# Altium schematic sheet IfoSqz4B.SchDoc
size C; Engineer: Daniel Sigg; DocumentNumber: 9; SheetNumber: 21; SheetTotal: 33
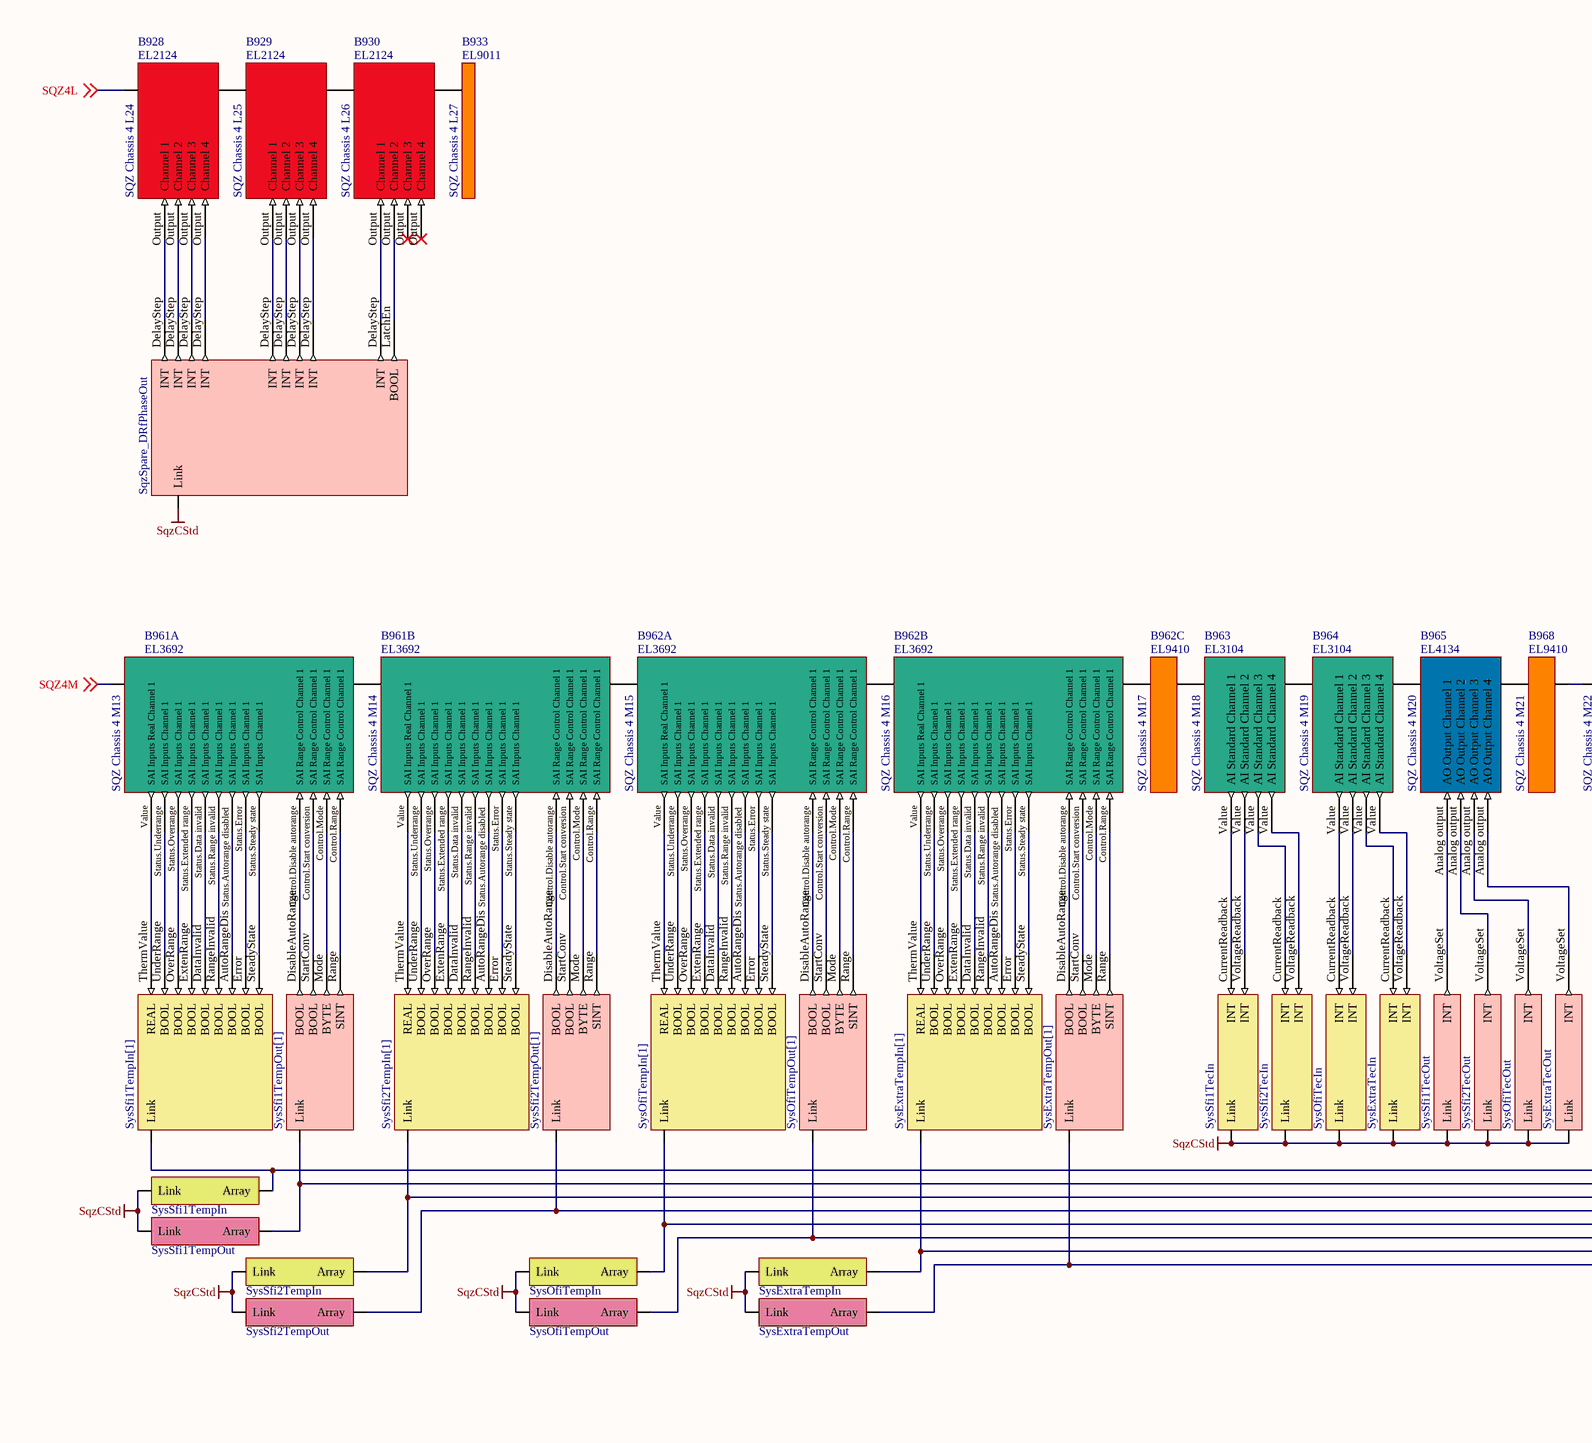
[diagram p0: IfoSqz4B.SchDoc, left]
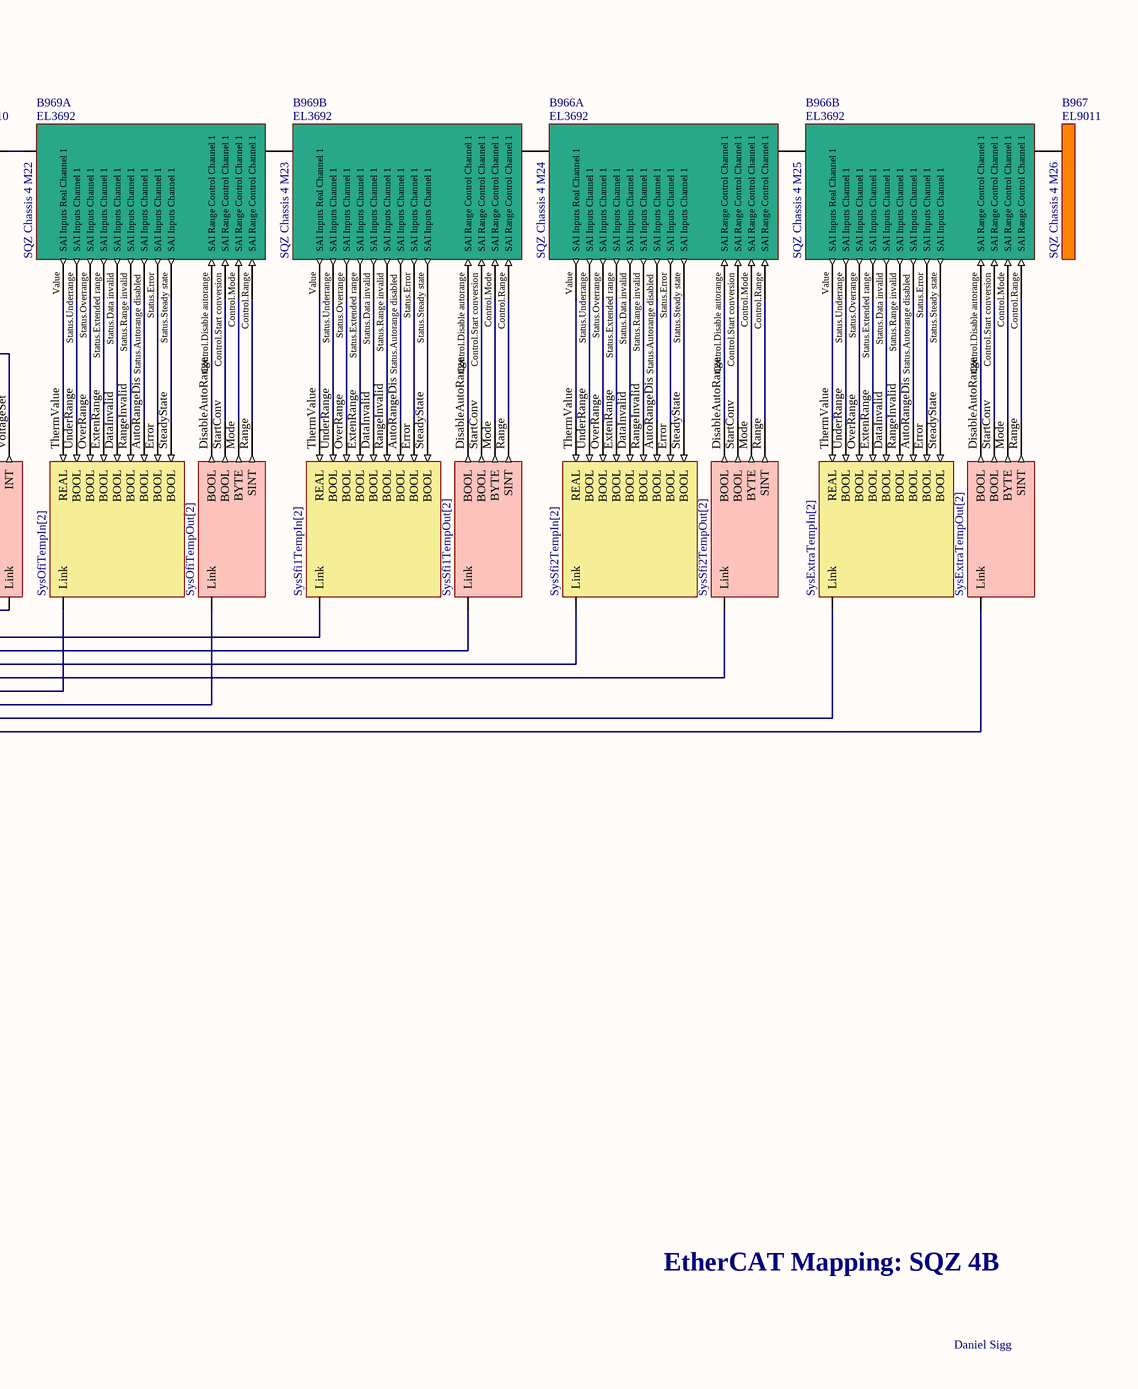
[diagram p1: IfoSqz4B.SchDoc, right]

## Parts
B928  SQZ Chassis 4 L24  Part Number: EL2124  (mechanical)
B929  SQZ Chassis 4 L25  Part Number: EL2124  (mechanical)
B930  SQZ Chassis 4 L26  Part Number: EL2124  (mechanical)
B933  SQZ Chassis 4 L27  Part Number: EL9011  (mechanical)
B961A  SQZ Chassis 4 M13  Part Number: EL3692  (mechanical)
B961B  SQZ Chassis 4 M14  Part Number: EL3692  (mechanical)
B962A  SQZ Chassis 4 M15  Part Number: EL3692  (mechanical)
B962B  SQZ Chassis 4 M16  Part Number: EL3692  (mechanical)
B962C  SQZ Chassis 4 M17  Part Number: EL9410  (mechanical)
B963  SQZ Chassis 4 M18  Part Number: EL3104  (mechanical)
B964  SQZ Chassis 4 M19  Part Number: EL3104  (mechanical)
B965  SQZ Chassis 4 M20  Part Number: EL4134  (mechanical)
B966A  SQZ Chassis 4 M24  Part Number: EL3692  (mechanical)
B966B  SQZ Chassis 4 M25  Part Number: EL3692  (mechanical)
B967  SQZ Chassis 4 M26  Part Number: EL9011  (mechanical)
B968  SQZ Chassis 4 M21  Part Number: EL9410  (mechanical)
B969A  SQZ Chassis 4 M22  Part Number: EL3692  (mechanical)
B969B  SQZ Chassis 4 M23  Part Number: EL3692  (mechanical)
V746  SqzSpare_DRfPhaseOut  (no BOM)
V750  SysOfiTempIn[2]  (no BOM)
V751  SysOfiTempOut[2]  (no BOM)
V752  SysSfi1TempIn[2]  (no BOM)
V753  SysSfi1TempOut[2]  (no BOM)
V754  SysOfiTempIn[1]  (no BOM)
V755  SysOfiTempOut[1]  (no BOM)
V756  SysSfi1TempIn[1]  (no BOM)
V757  SysSfi1TempOut[1]  (no BOM)
V758  SysSfi2TempIn[1]  (no BOM)
V759  SysSfi2TempOut[1]  (no BOM)
V760  SysExtraTempIn[1]  (no BOM)
V761  SysExtraTempOut[1]  (no BOM)
V762  SysOfiTecIn  (no BOM)
V763  SysSfi1TecIn  (no BOM)
V764  SysSfi2TecIn  (no BOM)
V765  SysExtraTecIn  (no BOM)
V766  SysOfiTecOut  (no BOM)
V767  SysSfi1TecOut  (no BOM)
V768  SysSfi2TecOut  (no BOM)
V769  SysExtraTecOut  (no BOM)
V770  SysSfi2TempIn[2]  (no BOM)
V771  SysSfi2TempOut[2]  (no BOM)
V772  SysExtraTempIn[2]  (no BOM)
V773  SysExtraTempOut[2]  (no BOM)
V788  SysOfiTempIn  (no BOM)
V789  SysOfiTempOut  (no BOM)
V790  SysSfi1TempIn  (no BOM)
V791  SysSfi2TempIn  (no BOM)
V792  SysExtraTempIn  (no BOM)
V793  SysSfi1TempOut  (no BOM)
V794  SysSfi2TempOut  (no BOM)
V795  SysExtraTempOut  (no BOM)

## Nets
SqzCStd: V746.?1(Link) V762.1(Link) V763.1(Link) V764.1(Link) V765.1(Link) V766.1(Link) V767.1(Link) V768.1(Link) V769.1(Link) V788.?1(Link) V789.?1(Link) V790.?1(Link) V791.?1(Link) V792.?1(Link) V793.?1(Link) V794.?1(Link) V795.?1(Link)
SQZ4L: B928.Ebus(A) ; off-sheet SQZ4L
SQZ4M: B961A.Ebus(A) ; off-sheet SQZ4M
NetB928_Ebus: B928.Ebus(B) B929.Ebus(A)
NetB928_Output: B928.Output(Channel_1) V746.DelayStep(INT)
NetB928_Output: B928.Output(Channel_2) V746.DelayStep(INT)  [a separate net that carries the same name]
NetB928_Output: B928.Output(Channel_3) V746.DelayStep(INT)  [a separate net that carries the same name]
NetB928_Output: B928.Output(Channel_4) V746.DelayStep(INT)  [a separate net that carries the same name]
NetB929_Ebus: B929.Ebus(B) B930.Ebus(A)
NetB929_Output: B929.Output(Channel_1) V746.DelayStep(INT)
NetB929_Output: B929.Output(Channel_2) V746.DelayStep(INT)  [a separate net that carries the same name]
NetB929_Output: B929.Output(Channel_3) V746.DelayStep(INT)  [a separate net that carries the same name]
NetB929_Output: B929.Output(Channel_4) V746.DelayStep(INT)  [a separate net that carries the same name]
NetB930_Ebus: B930.Ebus(B) B933.Ebus(A)
NetB930_Output: B930.Output(Channel_1) V746.DelayStep(INT)
NetB930_Output: B930.Output(Channel_2) V746.LatchEn(BOOL)  [a separate net that carries the same name]
NetB961A_Control.Disable autorange: B961A.Control.Disable_autorange(SAI_Range_Control_Channel_1) V757.DisableAutoRange(BOOL)
NetB961A_Control.Mode: B961A.Control.Mode(SAI_Range_Control_Channel_1) V757.Mode(BYTE)
NetB961A_Control.Range: B961A.Control.Range(SAI_Range_Control_Channel_1) V757.Range(SINT)
NetB961A_Control.Start conversion: B961A.Control.Start_conversion(SAI_Range_Control_Channel_1) V757.StartConv(BOOL)
NetB961A_Ebus: B961A.Ebus(B) B961B.Ebus(A)
NetB961A_Status.Autorange disabled: B961A.Status.Autorange_disabled(SAI_Inputs_Channel_1) V756.AutoRangeDis(BOOL)
NetB961A_Status.Data invalid: B961A.Status.Data_invalid(SAI_Inputs_Channel_1) V756.DataInvalid(BOOL)
NetB961A_Status.Error: B961A.Status.Error(SAI_Inputs_Channel_1) V756.Error(BOOL)
NetB961A_Status.Extended range: B961A.Status.Extended_range(SAI_Inputs_Channel_1) V756.ExtenRange(BOOL)
NetB961A_Status.Overrange: B961A.Status.Overrange(SAI_Inputs_Channel_1) V756.OverRange(BOOL)
NetB961A_Status.Range invalid: B961A.Status.Range_invalid(SAI_Inputs_Channel_1) V756.RangeInvalid(BOOL)
NetB961A_Status.Steady state: B961A.Status.Steady_state(SAI_Inputs_Channel_1) V756.SteadyState(BOOL)
NetB961A_Status.Underrange: B961A.Status.Underrange(SAI_Inputs_Channel_1) V756.UnderRange(BOOL)
NetB961A_Value: B961A.Value(SAI_Inputs_Real_Channel_1) V756.ThermValue(REAL)
NetB961B_Control.Disable autorange: B961B.Control.Disable_autorange(SAI_Range_Control_Channel_1) V759.DisableAutoRange(BOOL)
NetB961B_Control.Mode: B961B.Control.Mode(SAI_Range_Control_Channel_1) V759.Mode(BYTE)
NetB961B_Control.Range: B961B.Control.Range(SAI_Range_Control_Channel_1) V759.Range(SINT)
NetB961B_Control.Start conversion: B961B.Control.Start_conversion(SAI_Range_Control_Channel_1) V759.StartConv(BOOL)
NetB961B_Ebus: B961B.Ebus(B) B962A.Ebus(A)
NetB961B_Status.Autorange disabled: B961B.Status.Autorange_disabled(SAI_Inputs_Channel_1) V758.AutoRangeDis(BOOL)
NetB961B_Status.Data invalid: B961B.Status.Data_invalid(SAI_Inputs_Channel_1) V758.DataInvalid(BOOL)
NetB961B_Status.Error: B961B.Status.Error(SAI_Inputs_Channel_1) V758.Error(BOOL)
NetB961B_Status.Extended range: B961B.Status.Extended_range(SAI_Inputs_Channel_1) V758.ExtenRange(BOOL)
NetB961B_Status.Overrange: B961B.Status.Overrange(SAI_Inputs_Channel_1) V758.OverRange(BOOL)
NetB961B_Status.Range invalid: B961B.Status.Range_invalid(SAI_Inputs_Channel_1) V758.RangeInvalid(BOOL)
NetB961B_Status.Steady state: B961B.Status.Steady_state(SAI_Inputs_Channel_1) V758.SteadyState(BOOL)
NetB961B_Status.Underrange: B961B.Status.Underrange(SAI_Inputs_Channel_1) V758.UnderRange(BOOL)
NetB961B_Value: B961B.Value(SAI_Inputs_Real_Channel_1) V758.ThermValue(REAL)
NetB962A_Control.Disable autorange: B962A.Control.Disable_autorange(SAI_Range_Control_Channel_1) V755.DisableAutoRange(BOOL)
NetB962A_Control.Mode: B962A.Control.Mode(SAI_Range_Control_Channel_1) V755.Mode(BYTE)
NetB962A_Control.Range: B962A.Control.Range(SAI_Range_Control_Channel_1) V755.Range(SINT)
NetB962A_Control.Start conversion: B962A.Control.Start_conversion(SAI_Range_Control_Channel_1) V755.StartConv(BOOL)
NetB962A_Ebus: B962A.Ebus(B) B962B.Ebus(A)
NetB962A_Status.Autorange disabled: B962A.Status.Autorange_disabled(SAI_Inputs_Channel_1) V754.AutoRangeDis(BOOL)
NetB962A_Status.Data invalid: B962A.Status.Data_invalid(SAI_Inputs_Channel_1) V754.DataInvalid(BOOL)
NetB962A_Status.Error: B962A.Status.Error(SAI_Inputs_Channel_1) V754.Error(BOOL)
NetB962A_Status.Extended range: B962A.Status.Extended_range(SAI_Inputs_Channel_1) V754.ExtenRange(BOOL)
NetB962A_Status.Overrange: B962A.Status.Overrange(SAI_Inputs_Channel_1) V754.OverRange(BOOL)
NetB962A_Status.Range invalid: B962A.Status.Range_invalid(SAI_Inputs_Channel_1) V754.RangeInvalid(BOOL)
NetB962A_Status.Steady state: B962A.Status.Steady_state(SAI_Inputs_Channel_1) V754.SteadyState(BOOL)
NetB962A_Status.Underrange: B962A.Status.Underrange(SAI_Inputs_Channel_1) V754.UnderRange(BOOL)
NetB962A_Value: B962A.Value(SAI_Inputs_Real_Channel_1) V754.ThermValue(REAL)
NetB962B_Control.Disable autorange: B962B.Control.Disable_autorange(SAI_Range_Control_Channel_1) V761.DisableAutoRange(BOOL)
NetB962B_Control.Mode: B962B.Control.Mode(SAI_Range_Control_Channel_1) V761.Mode(BYTE)
NetB962B_Control.Range: B962B.Control.Range(SAI_Range_Control_Channel_1) V761.Range(SINT)
NetB962B_Control.Start conversion: B962B.Control.Start_conversion(SAI_Range_Control_Channel_1) V761.StartConv(BOOL)
NetB962B_Ebus: B962B.Ebus(B) B962C.Ebus(A)
NetB962B_Status.Autorange disabled: B962B.Status.Autorange_disabled(SAI_Inputs_Channel_1) V760.AutoRangeDis(BOOL)
NetB962B_Status.Data invalid: B962B.Status.Data_invalid(SAI_Inputs_Channel_1) V760.DataInvalid(BOOL)
NetB962B_Status.Error: B962B.Status.Error(SAI_Inputs_Channel_1) V760.Error(BOOL)
NetB962B_Status.Extended range: B962B.Status.Extended_range(SAI_Inputs_Channel_1) V760.ExtenRange(BOOL)
NetB962B_Status.Overrange: B962B.Status.Overrange(SAI_Inputs_Channel_1) V760.OverRange(BOOL)
NetB962B_Status.Range invalid: B962B.Status.Range_invalid(SAI_Inputs_Channel_1) V760.RangeInvalid(BOOL)
NetB962B_Status.Steady state: B962B.Status.Steady_state(SAI_Inputs_Channel_1) V760.SteadyState(BOOL)
NetB962B_Status.Underrange: B962B.Status.Underrange(SAI_Inputs_Channel_1) V760.UnderRange(BOOL)
NetB962B_Value: B962B.Value(SAI_Inputs_Real_Channel_1) V760.ThermValue(REAL)
NetB962C_Ebus: B962C.Ebus(B) B963.Ebus(A)
NetB963_Ebus: B963.Ebus(B) B964.Ebus(A)
NetB963_Value: B963.Value(AI_Standard_Channel_1) V763.CurrentReadback(INT)
NetB963_Value: B963.Value(AI_Standard_Channel_2) V763.VoltageReadback(INT)  [a separate net that carries the same name]
NetB963_Value: B963.Value(AI_Standard_Channel_3) V764.CurrentReadback(INT)  [a separate net that carries the same name]
NetB963_Value: B963.Value(AI_Standard_Channel_4) V764.VoltageReadback(INT)  [a separate net that carries the same name]
NetB964_Ebus: B964.Ebus(B) B965.Ebus(A)
NetB964_Value: B964.Value(AI_Standard_Channel_2) V762.VoltageReadback(INT)
NetB964_Value: B964.Value(AI_Standard_Channel_1) V762.CurrentReadback(INT)  [a separate net that carries the same name]
NetB964_Value: B964.Value(AI_Standard_Channel_3) V765.CurrentReadback(INT)  [a separate net that carries the same name]
NetB964_Value: B964.Value(AI_Standard_Channel_4) V765.VoltageReadback(INT)  [a separate net that carries the same name]
NetB965_Analog output: B965.Analog_output(AO_Output_Channel_1) V767.VoltageSet(INT)
NetB965_Analog output: B965.Analog_output(AO_Output_Channel_2) V768.VoltageSet(INT)  [a separate net that carries the same name]
NetB965_Analog output: B965.Analog_output(AO_Output_Channel_3) V766.VoltageSet(INT)  [a separate net that carries the same name]
NetB965_Analog output: B965.Analog_output(AO_Output_Channel_4) V769.VoltageSet(INT)  [a separate net that carries the same name]
NetB965_Ebus: B965.Ebus(B) B968.Ebus(A)
NetB966A_Control.Disable autorange: B966A.Control.Disable_autorange(SAI_Range_Control_Channel_1) V771.DisableAutoRange(BOOL)
NetB966A_Control.Mode: B966A.Control.Mode(SAI_Range_Control_Channel_1) V771.Mode(BYTE)
NetB966A_Control.Range: B966A.Control.Range(SAI_Range_Control_Channel_1) V771.Range(SINT)
NetB966A_Control.Start conversion: B966A.Control.Start_conversion(SAI_Range_Control_Channel_1) V771.StartConv(BOOL)
NetB966A_Ebus: B966A.Ebus(B) B966B.Ebus(A)
NetB966A_Ebus: B966A.Ebus(A) B969B.Ebus(B)  [a separate net that carries the same name]
NetB966A_Status.Autorange disabled: B966A.Status.Autorange_disabled(SAI_Inputs_Channel_1) V770.AutoRangeDis(BOOL)
NetB966A_Status.Data invalid: B966A.Status.Data_invalid(SAI_Inputs_Channel_1) V770.DataInvalid(BOOL)
NetB966A_Status.Error: B966A.Status.Error(SAI_Inputs_Channel_1) V770.Error(BOOL)
NetB966A_Status.Extended range: B966A.Status.Extended_range(SAI_Inputs_Channel_1) V770.ExtenRange(BOOL)
NetB966A_Status.Overrange: B966A.Status.Overrange(SAI_Inputs_Channel_1) V770.OverRange(BOOL)
NetB966A_Status.Range invalid: B966A.Status.Range_invalid(SAI_Inputs_Channel_1) V770.RangeInvalid(BOOL)
NetB966A_Status.Steady state: B966A.Status.Steady_state(SAI_Inputs_Channel_1) V770.SteadyState(BOOL)
NetB966A_Status.Underrange: B966A.Status.Underrange(SAI_Inputs_Channel_1) V770.UnderRange(BOOL)
NetB966A_Value: B966A.Value(SAI_Inputs_Real_Channel_1) V770.ThermValue(REAL)
NetB966B_Control.Disable autorange: B966B.Control.Disable_autorange(SAI_Range_Control_Channel_1) V773.DisableAutoRange(BOOL)
NetB966B_Control.Mode: B966B.Control.Mode(SAI_Range_Control_Channel_1) V773.Mode(BYTE)
NetB966B_Control.Range: B966B.Control.Range(SAI_Range_Control_Channel_1) V773.Range(SINT)
NetB966B_Control.Start conversion: B966B.Control.Start_conversion(SAI_Range_Control_Channel_1) V773.StartConv(BOOL)
NetB966B_Ebus: B966B.Ebus(B) B967.Ebus(A)
NetB966B_Status.Autorange disabled: B966B.Status.Autorange_disabled(SAI_Inputs_Channel_1) V772.AutoRangeDis(BOOL)
NetB966B_Status.Data invalid: B966B.Status.Data_invalid(SAI_Inputs_Channel_1) V772.DataInvalid(BOOL)
NetB966B_Status.Error: B966B.Status.Error(SAI_Inputs_Channel_1) V772.Error(BOOL)
NetB966B_Status.Extended range: B966B.Status.Extended_range(SAI_Inputs_Channel_1) V772.ExtenRange(BOOL)
NetB966B_Status.Overrange: B966B.Status.Overrange(SAI_Inputs_Channel_1) V772.OverRange(BOOL)
NetB966B_Status.Range invalid: B966B.Status.Range_invalid(SAI_Inputs_Channel_1) V772.RangeInvalid(BOOL)
NetB966B_Status.Steady state: B966B.Status.Steady_state(SAI_Inputs_Channel_1) V772.SteadyState(BOOL)
NetB966B_Status.Underrange: B966B.Status.Underrange(SAI_Inputs_Channel_1) V772.UnderRange(BOOL)
NetB966B_Value: B966B.Value(SAI_Inputs_Real_Channel_1) V772.ThermValue(REAL)
NetB968_Ebus: B968.Ebus(B) B969A.Ebus(A)
NetB969A_Control.Disable autorange: B969A.Control.Disable_autorange(SAI_Range_Control_Channel_1) V751.DisableAutoRange(BOOL)
NetB969A_Control.Mode: B969A.Control.Mode(SAI_Range_Control_Channel_1) V751.Mode(BYTE)
NetB969A_Control.Range: B969A.Control.Range(SAI_Range_Control_Channel_1) V751.Range(SINT)
NetB969A_Control.Start conversion: B969A.Control.Start_conversion(SAI_Range_Control_Channel_1) V751.StartConv(BOOL)
NetB969A_Ebus: B969A.Ebus(B) B969B.Ebus(A)
NetB969A_Status.Autorange disabled: B969A.Status.Autorange_disabled(SAI_Inputs_Channel_1) V750.AutoRangeDis(BOOL)
NetB969A_Status.Data invalid: B969A.Status.Data_invalid(SAI_Inputs_Channel_1) V750.DataInvalid(BOOL)
NetB969A_Status.Error: B969A.Status.Error(SAI_Inputs_Channel_1) V750.Error(BOOL)
NetB969A_Status.Extended range: B969A.Status.Extended_range(SAI_Inputs_Channel_1) V750.ExtenRange(BOOL)
NetB969A_Status.Overrange: B969A.Status.Overrange(SAI_Inputs_Channel_1) V750.OverRange(BOOL)
NetB969A_Status.Range invalid: B969A.Status.Range_invalid(SAI_Inputs_Channel_1) V750.RangeInvalid(BOOL)
NetB969A_Status.Steady state: B969A.Status.Steady_state(SAI_Inputs_Channel_1) V750.SteadyState(BOOL)
NetB969A_Status.Underrange: B969A.Status.Underrange(SAI_Inputs_Channel_1) V750.UnderRange(BOOL)
NetB969A_Value: B969A.Value(SAI_Inputs_Real_Channel_1) V750.ThermValue(REAL)
NetB969B_Control.Disable autorange: B969B.Control.Disable_autorange(SAI_Range_Control_Channel_1) V753.DisableAutoRange(BOOL)
NetB969B_Control.Mode: B969B.Control.Mode(SAI_Range_Control_Channel_1) V753.Mode(BYTE)
NetB969B_Control.Range: B969B.Control.Range(SAI_Range_Control_Channel_1) V753.Range(SINT)
NetB969B_Control.Start conversion: B969B.Control.Start_conversion(SAI_Range_Control_Channel_1) V753.StartConv(BOOL)
NetB969B_Status.Autorange disabled: B969B.Status.Autorange_disabled(SAI_Inputs_Channel_1) V752.AutoRangeDis(BOOL)
NetB969B_Status.Data invalid: B969B.Status.Data_invalid(SAI_Inputs_Channel_1) V752.DataInvalid(BOOL)
NetB969B_Status.Error: B969B.Status.Error(SAI_Inputs_Channel_1) V752.Error(BOOL)
NetB969B_Status.Extended range: B969B.Status.Extended_range(SAI_Inputs_Channel_1) V752.ExtenRange(BOOL)
NetB969B_Status.Overrange: B969B.Status.Overrange(SAI_Inputs_Channel_1) V752.OverRange(BOOL)
NetB969B_Status.Range invalid: B969B.Status.Range_invalid(SAI_Inputs_Channel_1) V752.RangeInvalid(BOOL)
NetB969B_Status.Steady state: B969B.Status.Steady_state(SAI_Inputs_Channel_1) V752.SteadyState(BOOL)
NetB969B_Status.Underrange: B969B.Status.Underrange(SAI_Inputs_Channel_1) V752.UnderRange(BOOL)
NetB969B_Value: B969B.Value(SAI_Inputs_Real_Channel_1) V752.ThermValue(REAL)
NetV750_1: V750.1(Link) V754.1(Link) V788.?2(Array)
NetV751_1: V751.1(Link) V755.1(Link) V789.?2(Array)
NetV752_1: V752.1(Link) V756.1(Link) V790.?2(Array)
NetV753_1: V753.1(Link) V757.1(Link) V793.?2(Array)
NetV758_1: V758.1(Link) V770.1(Link) V791.?2(Array)
NetV759_1: V759.1(Link) V771.1(Link) V794.?2(Array)
NetV760_1: V760.1(Link) V772.1(Link) V792.?2(Array)
NetV761_1: V761.1(Link) V773.1(Link) V795.?2(Array)

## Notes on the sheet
- EtherCAT Mapping: SQZ 4B
- Daniel Sigg

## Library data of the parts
B928 = TerminalEL2124: EtherCAT Terminal EL2124 4-chn Digital Ouput; Rail: Left; BoxNextB: OIWCCIRA; BoxPrev: IKRYUTNI; PortPrevFull: 1210/B; PortPrevShort: B; Fullname: TIID^Vertex Squeezer (EtherCAT)^SQZ Chassis 4 L0 (EK1101)^SQZ Chassis 4 L24 (EL2124); BoxAddr: 1211; Disabled: False
B929 = TerminalEL2124: EtherCAT Terminal EL2124 4-chn Digital Ouput; Rail: Left; BoxNextB: OJTEBPAB; BoxPrev: SBVBAHED; PortPrevFull: 1211/B; PortPrevShort: B; Fullname: TIID^Vertex Squeezer (EtherCAT)^SQZ Chassis 4 L0 (EK1101)^SQZ Chassis 4 L25 (EL2124); BoxAddr: 1212; Disabled: False
B930 = TerminalEL2124: EtherCAT Terminal EL2124 4-chn Digital Ouput; Rail: Left; BoxNextB: NRHBNLIL; BoxPrev: OIWCCIRA; PortPrevFull: 1212/B; PortPrevShort: B; Fullname: TIID^Vertex Squeezer (EtherCAT)^SQZ Chassis 4 L0 (EK1101)^SQZ Chassis 4 L26 (EL2124); BoxAddr: 1213; Disabled: False
B933 = TerminalEL9011: EtherCAT Terminal EL9011 End; BoxType: TerminalPassive; Rail: Left; BoxPrev: OJTEBPAB; PortPrevShort: B; Fullname: TIID^Vertex Squeezer (EtherCAT)^SQZ Chassis 4 L0 (EK1101)^SQZ Chassis 4 L27 (EL9011); Disabled: False
B961A = TerminalEL3692-1chn: EtherCAT Terminal EL3692 1-chn Resistance Measurement; Rail: Middle; BoxNextB: UBNVSPGB; BoxPrev: SXFJKERQ; PortPrevFull: 1226/B; PortPrevShort: B; Fullname: TIID^Vertex Squeezer (EtherCAT)^SQZ Chassis 4 M0 (EK1100)^SQZ Chassis 4 M13 (EL3692); BoxAddr: 1227; PDO Inputs: 0x1A00,0x1A02; PDO Outputs: 0x1600; Disabled: False
B961B = TerminalEL3692-1chn: EtherCAT Terminal EL3692 1-chn Resistance Measurement; Rail: Middle; BoxNextB: ALHVDIEX; BoxPrev: XCBOHHOF; PortPrevFull: 1227/B; PortPrevShort: B; Fullname: TIID^Vertex Squeezer (EtherCAT)^SQZ Chassis 4 M0 (EK1100)^SQZ Chassis 4 M14 (EL3692); BoxAddr: 1228; PDO Inputs: 0x1A00,0x1A02; PDO Outputs: 0x1600; Disabled: False
B962A = TerminalEL3692-1chn: EtherCAT Terminal EL3692 1-chn Resistance Measurement; Rail: Middle; BoxNextB: TFRQXLOH; BoxPrev: UBNVSPGB; PortPrevFull: 1228/B; PortPrevShort: B; Fullname: TIID^Vertex Squeezer (EtherCAT)^SQZ Chassis 4 M0 (EK1100)^SQZ Chassis 4 M15 (EL3692); BoxAddr: 1229; PDO Inputs: 0x1A00,0x1A02; PDO Outputs: 0x1600; Disabled: False
B962B = TerminalEL3692-1chn: EtherCAT Terminal EL3692 1-chn Resistance Measurement; Rail: Middle; BoxNextB: ZDXOLKQL; BoxPrev: ALHVDIEX; PortPrevFull: 1229/B; PortPrevShort: B; Fullname: TIID^Vertex Squeezer (EtherCAT)^SQZ Chassis 4 M0 (EK1100)^SQZ Chassis 4 M16 (EL3692); BoxAddr: 1230; PDO Inputs: 0x1A00,0x1A02; PDO Outputs: 0x1600; Disabled: False
B962C = TerminalEL9410: EtherCAT Terminal EL9410 Power; Rail: Middle; BoxNextB: POYUXNSI; BoxPrev: TFRQXLOH; PortPrevFull: 1230/B; PortPrevShort: B; Fullname: TIID^Vertex Squeezer (EtherCAT)^SQZ Chassis 4 M0 (EK1100)^SQZ Chassis 4 M17 (EL9410); BoxAddr: 1231; Disabled: False
B963 = TerminalEL3104: EtherCAT Terminal EL3104 4-chn Analog Input; Rail: Middle; BoxNextB: WNKQTDTO; BoxPrev: ZDXOLKQL; PortPrevFull: 1231/B; PortPrevShort: B; Fullname: TIID^Vertex Squeezer (EtherCAT)^SQZ Chassis 4 M0 (EK1100)^SQZ Chassis 4 M18 (EL3104); BoxAddr: 1232; Disabled: False
B964 = TerminalEL3104: EtherCAT Terminal EL3104 4-chn Analog Input; Rail: Middle; BoxNextB: MYVIGLKX; BoxPrev: POYUXNSI; PortPrevFull: 1232/B; PortPrevShort: B; Fullname: TIID^Vertex Squeezer (EtherCAT)^SQZ Chassis 4 M0 (EK1100)^SQZ Chassis 4 M19 (EL3104); BoxAddr: 1233; Disabled: False
B965 = TerminalEL4134: EtherCAT Terminal EL4134 4-chn Analog Ouput; Rail: Middle; BoxNextB: CVMEERUG; BoxPrev: WNKQTDTO; PortPrevFull: 1233/B; PortPrevShort: B; Fullname: TIID^Vertex Squeezer (EtherCAT)^SQZ Chassis 4 M0 (EK1100)^SQZ Chassis 4 M20 (EL4134); BoxAddr: 1234; Disabled: False
B966A = TerminalEL3692-1chn: EtherCAT Terminal EL3692 1-chn Resistance Measurement; Rail: Middle; BoxNextB: ACOCYMUJ; BoxPrev: CHKFXWZD; PortPrevFull: 1237/B; PortPrevShort: B; Fullname: TIID^Vertex Squeezer (EtherCAT)^SQZ Chassis 4 M0 (EK1100)^SQZ Chassis 4 M24 (EL3692); BoxAddr: 1238; PDO Inputs: 0x1A00,0x1A02; PDO Outputs: 0x1600; Disabled: False
B966B = TerminalEL3692-1chn: EtherCAT Terminal EL3692 1-chn Resistance Measurement; Rail: Middle; BoxNextB: OCCMWWTA; BoxPrev: CCHIHLWV; PortPrevFull: 1238/B; PortPrevShort: B; Fullname: TIID^Vertex Squeezer (EtherCAT)^SQZ Chassis 4 M0 (EK1100)^SQZ Chassis 4 M25 (EL3692); BoxAddr: 1239; PDO Inputs: 0x1A00,0x1A02; PDO Outputs: 0x1600; Disabled: False
B967 = TerminalEL9011: EtherCAT Terminal EL9011 End; BoxType: TerminalPassive; Rail: Middle; BoxPrev: ACOCYMUJ; PortPrevShort: B; Fullname: TIID^Vertex Squeezer (EtherCAT)^SQZ Chassis 4 M0 (EK1100)^SQZ Chassis 4 M26 (EL9011); Disabled: False
B968 = TerminalEL9410: EtherCAT Terminal EL9410 Power; Rail: Middle; BoxNextB: QXUBQGAJ; BoxPrev: MYVIGLKX; PortPrevFull: 1234/B; PortPrevShort: B; Fullname: TIID^Vertex Squeezer (EtherCAT)^SQZ Chassis 4 M0 (EK1100)^SQZ Chassis 4 M21 (EL9410); BoxAddr: 1235; Disabled: False
B969A = TerminalEL3692-1chn: EtherCAT Terminal EL3692 1-chn Resistance Measurement; Rail: Middle; BoxNextB: CHKFXWZD; BoxPrev: CVMEERUG; PortPrevFull: 1235/B; PortPrevShort: B; Fullname: TIID^Vertex Squeezer (EtherCAT)^SQZ Chassis 4 M0 (EK1100)^SQZ Chassis 4 M22 (EL3692); BoxAddr: 1236; PDO Inputs: 0x1A00,0x1A02; PDO Outputs: 0x1600; Disabled: False
B969B = TerminalEL3692-1chn: EtherCAT Terminal EL3692 1-chn Resistance Measurement; Rail: Middle; BoxNextB: CCHIHLWV; BoxPrev: QXUBQGAJ; PortPrevFull: 1236/B; PortPrevShort: B; Fullname: TIID^Vertex Squeezer (EtherCAT)^SQZ Chassis 4 M0 (EK1100)^SQZ Chassis 4 M23 (EL3692); BoxAddr: 1237; PDO Inputs: 0x1A00,0x1A02; PDO Outputs: 0x1600; Disabled: False
V746 = DelayLogic_DelayLogicOutStruct: DelayLogicOutStruct; BoxType: Variable; Instance: H1SqzCorner Instance; PLC: H1SqzCorner; Task: SqzCStd
V750 V752 V754 V756 V758 V760 V770 V772 = TECController_ThermistorInStruct: ThermistorInStruct; BoxType: Variable; Instance: H1SqzCorner Instance; PLC: H1SqzCorner; Task: SqzCStd
V751 V753 V755 V757 V759 V761 V771 V773 = TECController_ThermistorOutStruct: ThermistorOutStruct; BoxType: Variable; Instance: H1SqzCorner Instance; PLC: H1SqzCorner; Task: SqzCStd
V762-V765 = TECController_TECDriverInStruct: TECDriverInStruct; BoxType: Variable; Instance: H1SqzCorner Instance; PLC: H1SqzCorner; Task: SqzCStd
V766-V769 = TECController_TECDriverOutStruct: TECDriverOutStruct; BoxType: Variable; Instance: H1SqzCorner Instance; PLC: H1SqzCorner; Task: SqzCStd
V788 V790-V792 = ArrayAggregatorIn: Array [1..2] Of ThermistorInStruct; Instance: H1SqzCorner Instance; PLC: H1SqzCorner; Task: SqzCStd; Lower Bound: 1; Upper Bound: 2
V789 V793-V795 = ArrayAggregatorOut: Array [1..2] Of ThermistorOutStruct; Instance: H1SqzCorner Instance; PLC: H1SqzCorner; Task: SqzCStd; Lower Bound: 1; Upper Bound: 2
